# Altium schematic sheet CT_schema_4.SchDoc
size 394 x 358 mm
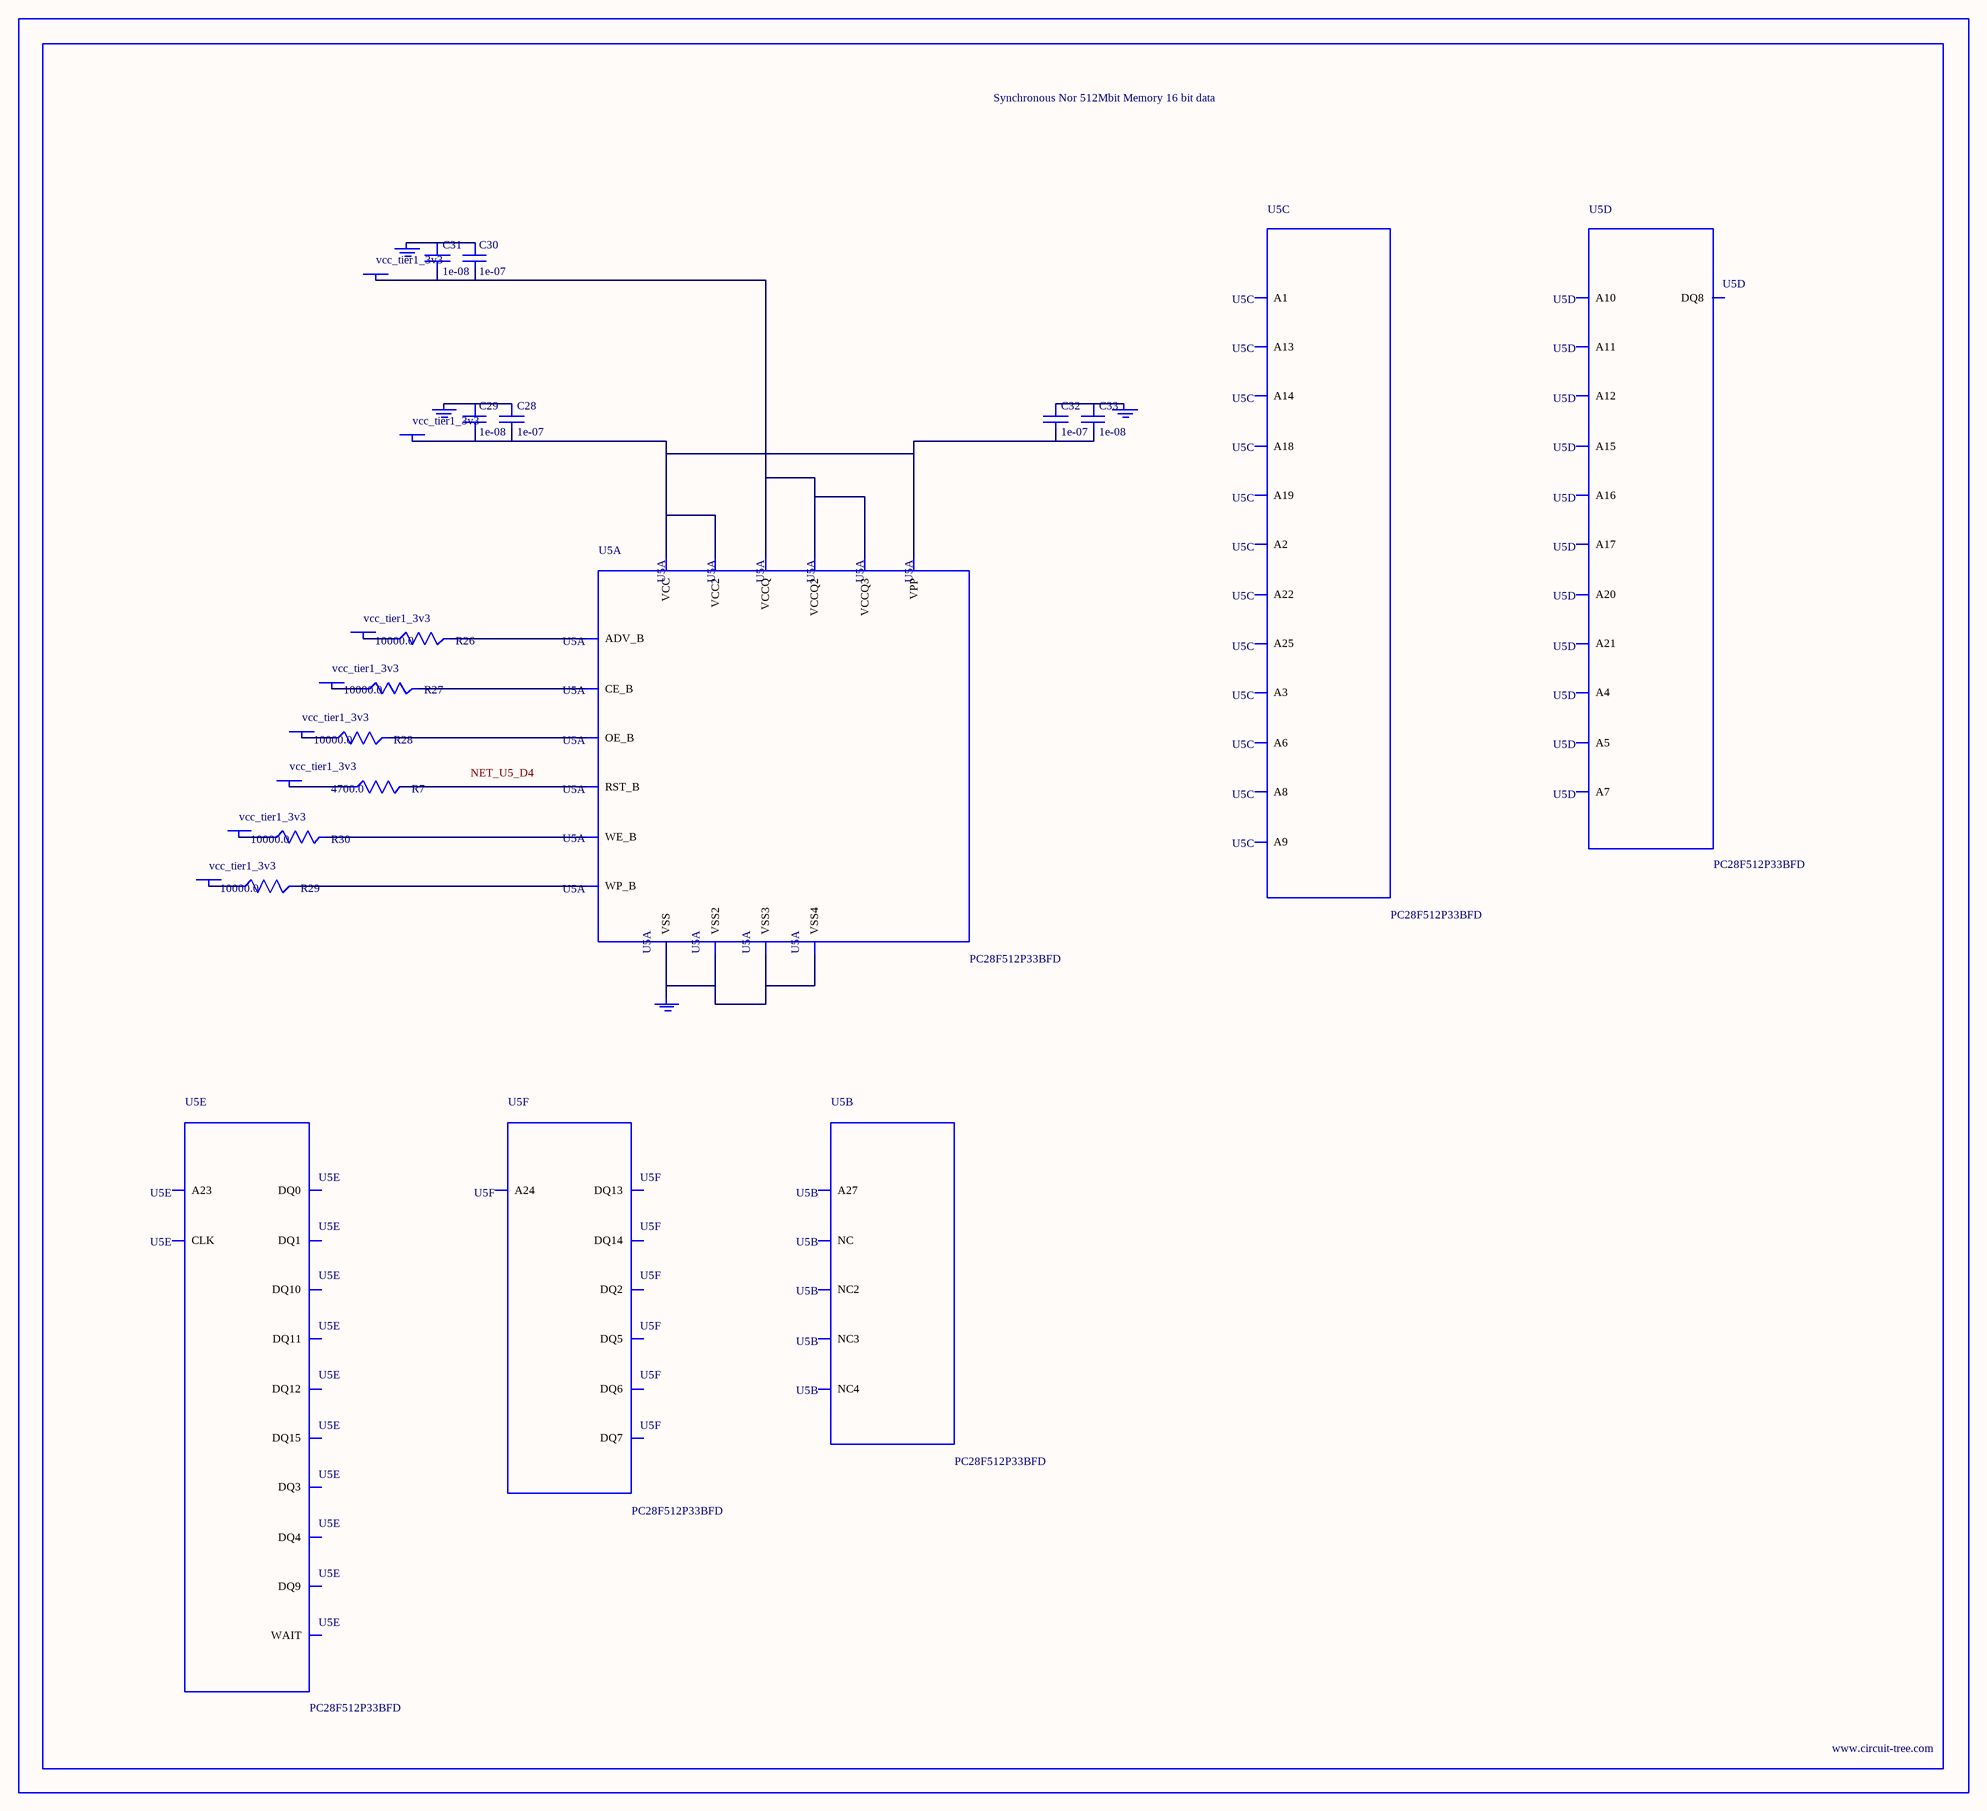
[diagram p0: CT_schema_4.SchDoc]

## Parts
BORDER3  (no value)
C28  1e-07  [C0402]
C29  1e-08  [C0402]
C30  1e-07  [C0402]
C31  1e-08  [C0402]
C32  1e-07  [C0402]
C33  1e-08  [C0402]
GND_INSTANCE_3_0  (no value)
GND_INSTANCE_3_1  (no value)
GND_INSTANCE_3_2  (no value)
GND_INSTANCE_3_3  (no value)
POWER_INSTANCE_3_0  vcc_tier1_3v3
POWER_INSTANCE_3_1  vcc_tier1_3v3
POWER_INSTANCE_3_2  vcc_tier1_3v3
POWER_INSTANCE_3_3  vcc_tier1_3v3
POWER_INSTANCE_3_4  vcc_tier1_3v3
POWER_INSTANCE_3_5  vcc_tier1_3v3
POWER_INSTANCE_3_6  vcc_tier1_3v3
POWER_INSTANCE_3_7  vcc_tier1_3v3
R7  4700.0  [R0603]
R26  10000.0  [R0603]
R27  10000.0  [R0603]
R28  10000.0  [R0603]
R29  10000.0  [R0603]
R30  10000.0  [R0603]
U5  PC28F512P33BFD  [PC28F512P33BFD]  (parts A,B,C,D,E,F of 6)

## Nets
NetC28_1: C28.1 C29.1 GND_INSTANCE_3_0.0(GND)
NetC28_2: C28.2 C29.2 C32.2 C33.2 POWER_INSTANCE_3_0.0(PWR) U5.A4(VPP) U5.A6(VCC) U5.H3(VCC2)
NetC30_1: C30.1 C31.1 GND_INSTANCE_3_1.0(GND)
NetC30_2: C30.2 C31.2 POWER_INSTANCE_3_1.0(PWR) U5.D5(VCCQ) U5.D6(VCCQ2) U5.G4(VCCQ3)
NetC32_1: C32.1 C33.1 GND_INSTANCE_3_2.0(GND)
NetGND_INSTANCE_3_3_0: GND_INSTANCE_3_3.0(GND) U5.B2(VSS) U5.H2(VSS2) U5.H4(VSS3) U5.H6(VSS4)
NetPOWER_INSTANCE_3_2_0: POWER_INSTANCE_3_2.0(PWR) R26.1
NetPOWER_INSTANCE_3_3_0: POWER_INSTANCE_3_3.0(PWR) R27.1
NetPOWER_INSTANCE_3_4_0: POWER_INSTANCE_3_4.0(PWR) R28.1
NetPOWER_INSTANCE_3_5_0: POWER_INSTANCE_3_5.0(PWR) R29.1
NetPOWER_INSTANCE_3_6_0: POWER_INSTANCE_3_6.0(PWR) R30.1
NetPOWER_INSTANCE_3_7_0: POWER_INSTANCE_3_7.0(PWR) R7.1
NetR7_2: R7.2 U5.D4(RST_B)
NetR26_2: R26.2 U5.F6(ADV_B)
NetR27_2: R27.2 U5.B4(CE_B)
NetR28_2: R28.2 U5.F8(OE_B)
NetR29_2: R29.2 U5.C6(WP_B)
NetR30_2: R30.2 U5.G8(WE_B)

Not connected (* = marked no-connect by the designer): U5 A1 A2(A6) A3(A8) A5(A13) A7(A18) A8(A22) B1(A2) B3(A9) B5(A14) B6(A25) B7(A19) B8(NC) C1(A3) C2(A7) C3(A10) C4(A12) C5(A15) C7(A20) C8(A21) D1(A4) D2(A5) D3(A11) D7(A16) D8(A17) E1(DQ8) E2(DQ1) E3(DQ9) E4(DQ3) E5(DQ4) E6(CLK) E7(DQ15) E8(NC2) F1(NC3) F2(DQ0) F3(DQ10) F4(DQ11) F5(DQ12) F7(WAIT) G1(A23) G2(NC4) G3(DQ2) G5(DQ5) G6(DQ6) G7(DQ14) H1(A27) H5(DQ13) H7(DQ7) H8(A24)

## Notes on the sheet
- Labels drawn without touching a wire or pin: NET_U5_D4

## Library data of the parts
BORDER3 = BORDER_PAGE3
C28 C30 C32 = C0402C104K3RACTU
C29 C31 C33 = C0402C103K3RAC
GND_INSTANCE_3_0-GND_INSTANCE_3_3 = GND
POWER_INSTANCE_3_0-POWER_INSTANCE_3_7 = PWR
R7 = RC0603JR-074K7L
R26-R30 = RC0603JR-0710KL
